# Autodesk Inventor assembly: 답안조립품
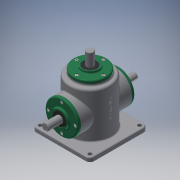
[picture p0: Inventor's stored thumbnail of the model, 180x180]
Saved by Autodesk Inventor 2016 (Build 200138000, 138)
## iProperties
Created: 2019-08
Part Number: 답안조립품
Material: 일반
Document SubType Name: Assembly
Designer: user
Author: user
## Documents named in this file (16)
- C:\Users\user\Desktop\490823V1009\답안조립품.iam
- C:\Users\user\Desktop\490823V1009\본체.ipt
- C:\Users\user\Desktop\490823V1009\메인 베벨기어.ipt
- C:\Users\user\Desktop\490823V1009\메인 축.ipt
- 메인 축.ipt
- C:\Users\user\Desktop\490823V1009\베어링 6203.ipt
- C:\Users\user\Desktop\490823V1009\볼트 M4.ipt
- 볼트 M4.ipt
- C:\Users\user\Desktop\490823V1009\서브 베벨기어.ipt
- C:\Users\user\Desktop\490823V1009\서브 축.ipt
- 서브 축.ipt
- C:\Users\user\Desktop\490823V1009\오일 실.ipt
- 오일 실.ipt
- C:\Users\user\Desktop\490823V1009\커버.ipt
- C:\Users\user\Desktop\490823V1009\키 4x4.ipt
- C:\Users\user\Desktop\490823V1009\키 5x5.ipt
